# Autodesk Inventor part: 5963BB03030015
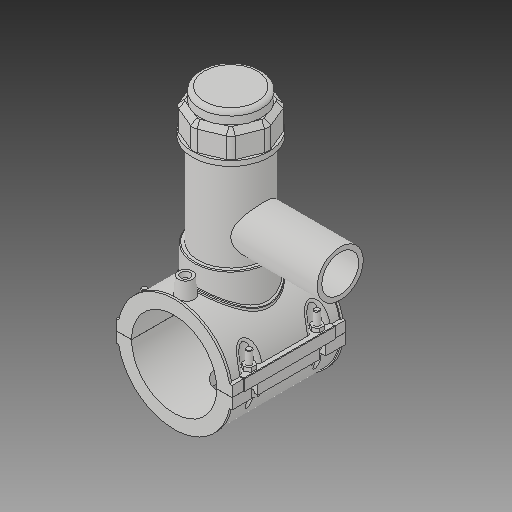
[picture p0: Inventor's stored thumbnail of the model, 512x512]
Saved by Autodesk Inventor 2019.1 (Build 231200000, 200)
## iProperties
Created: 2017-07
Part Number: 5963BB03030015
Material: Generic
Description: PLASSON TAPPING SADDLE 3''IPS x 1 1/2''IPS
Document SubType Name: Modeling
Designer: KIM
Mass: 1712.7 g
Surface Area: 2671.49 cm^2
Volume: 1712.7 cm^3
Density: 1 g/cm^3
Appearance: Default
Author: KIM
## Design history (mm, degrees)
derived "5963B.ipt"
feature "Solid1::5963B.ipt"
feature "Solid2::5963B.ipt"
feature "Solid4::5963B.ipt"
feature "Solid5::5963B.ipt"
tag "TaggingFeature1"
body "Solid1"
body "Solid2"
other parameters: "d0" = 88.7, "d2" = 120.904, "d3" = 22.175, "d4" = 118.11, "d5" = 0, "d6" = 0.1, "d8" = 0, "d19" = 6, "d20" = 6, "d21" = 70.866, "d23" = 0, "d24" = 35.433, "d26" = 0, "d29" = 3, "d30" = 29.56667, "d31" = 6, "d32" = 0, "d33" = 0, "d34" = 0.6, "d40" = 59.9612, "d41" = 79.83, "d43" = 0, "d45" = 0, "d47" = 128.521, "d70" = 15, "d72" = 0, "d73" = 6, "d75" = 5, "d76" = 0, "d77" = 4.435, "d78" = 74.35, "d79" = 15, "d80" = 47.244, "d82" = 5 deg, "d84" = 4, "d85" = 14, "d86" = 0, "d87" = 3, "d88" = 0, "d89" = 1, "d90" = 1, "d91" = 94.488, "d92" = 0, "d93" = 0.5, "d94" = 46.68421, "d96" = 117.6162, "d97" = 2.3622, "d98" = 0, "d102" = 0.887, "d120" = 140 deg, "d121" = 24.228, "d122" = 20 deg, "d123" = 230.62, "d124" = 69.186, "d126" = 0, "d143" = 91.361, "d145" = 20.46923, "d149" = 1.3305, "d150" = 22.51615, "d153" = 118.11, "d154" = 0, "d156" = 57.655, "d157" = 160 deg, "d159" = 5.322, "d161" = 1.3305, "d162" = 70.866, "d163" = 0, "d164" = 44.35, "d167" = 8.87, "d168" = 56.24878, "d170" = 3.2805, "d172" = 0, "d173" = 1, "d175" = 44.35, "d176" = 20 deg, "d177" = 6.209, "d178" = 26.61, "d180" = 0, "d183" = 10.644, "d184" = 4.9672, "d185" = 38.38575, "d186" = 38.38575, "d187" = 57.655, "d188" = 7.983, "d189" = 6.209, "d190" = 0, "d191" = 86.4825, "d193" = 6.1236, "d194" = 4.13385, "d195" = 90 deg, "d197" = 0, "d199" = 0, "d200" = 13.305, "d202" = 0, "d203" = 177.038, "d204" = 75.8385, "d205" = 55.881, "d206" = 67.8555, "d207" = 132.7785, "d208" = 138.08964, "d209" = 164.64534, "d210" = 68.6538, "d211" = 79.83, "d212" = 63.864, "d213" = 36.8766, "d216" = 0, "d217" = 8.87, "d218" = 4.435, "d219" = 0.887, "d222" = 88.7, "d224" = 0, "d230" = 5.322, "d233" = 6, "d236" = 60.452, "d237" = 35.433, "d238" = 6.02433, "d240" = 35.433, "d241" = 35.433, "d242" = 35.433, "d243" = 6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
